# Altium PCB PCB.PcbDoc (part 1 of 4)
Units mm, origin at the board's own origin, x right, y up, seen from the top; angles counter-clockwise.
Board outline 430 x 130 mm, 2 copper layers (Top Layer, Bottom Layer); 471 components, 267 nets, 1806 pads, 471 vias.
Unrouted connection lines stored in the file: 127.
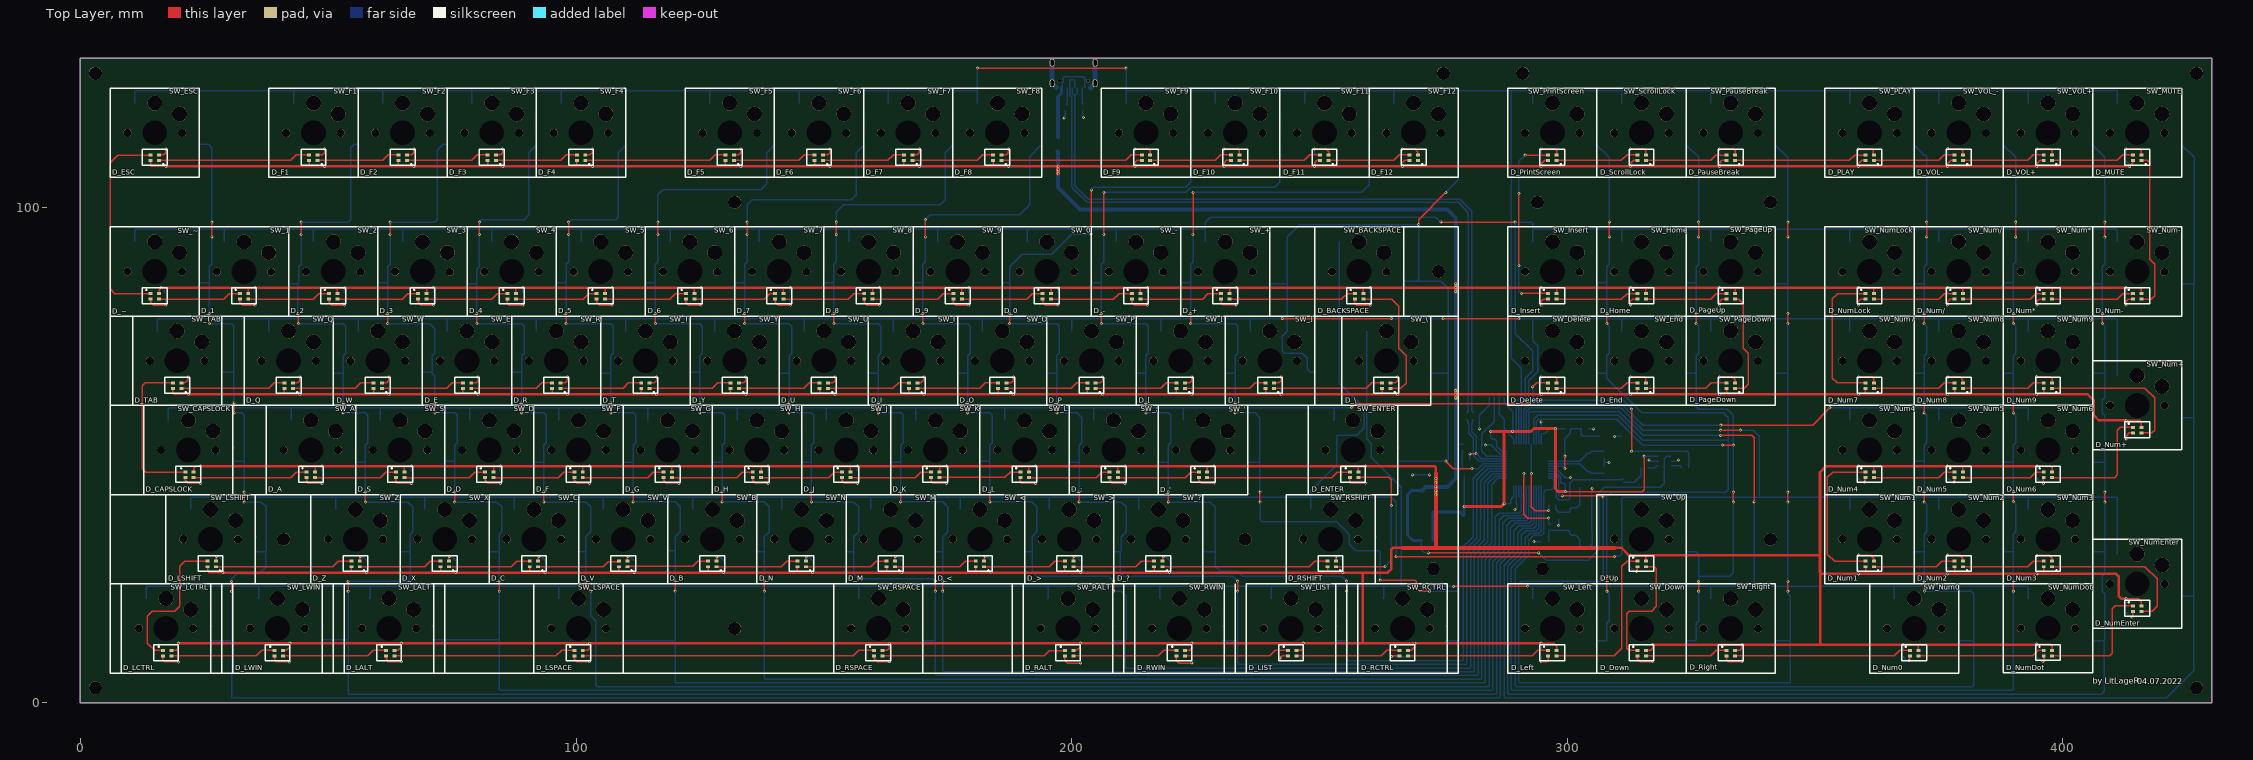
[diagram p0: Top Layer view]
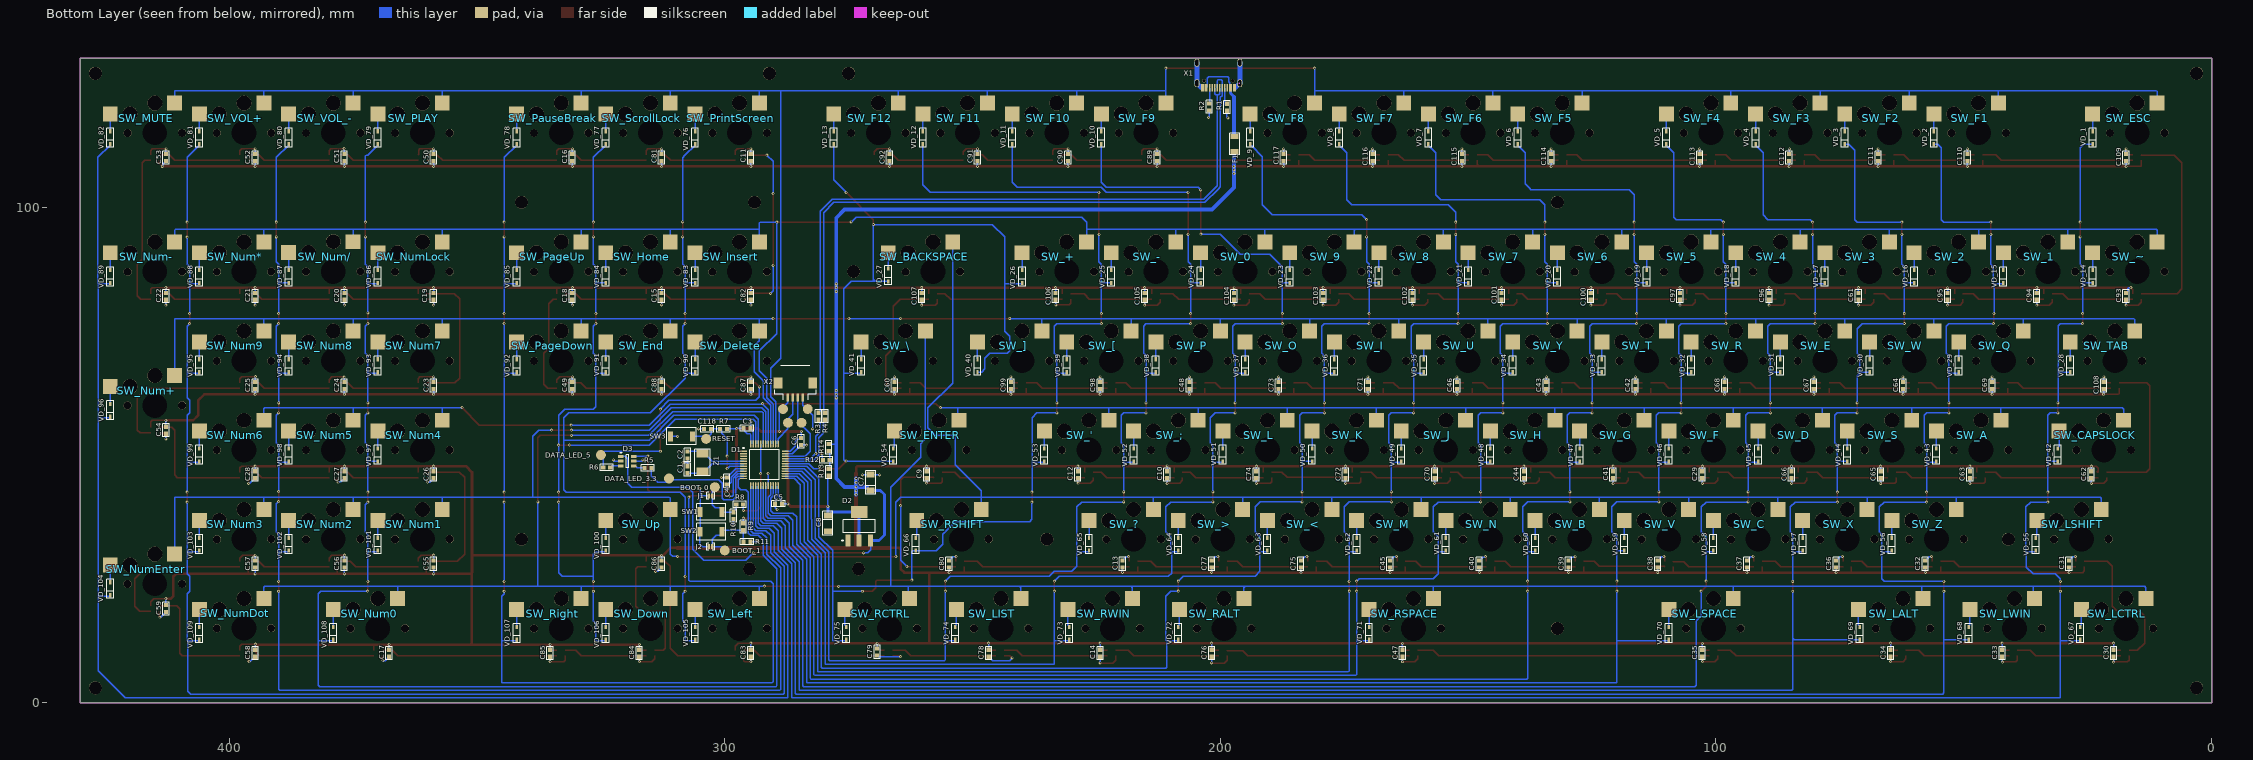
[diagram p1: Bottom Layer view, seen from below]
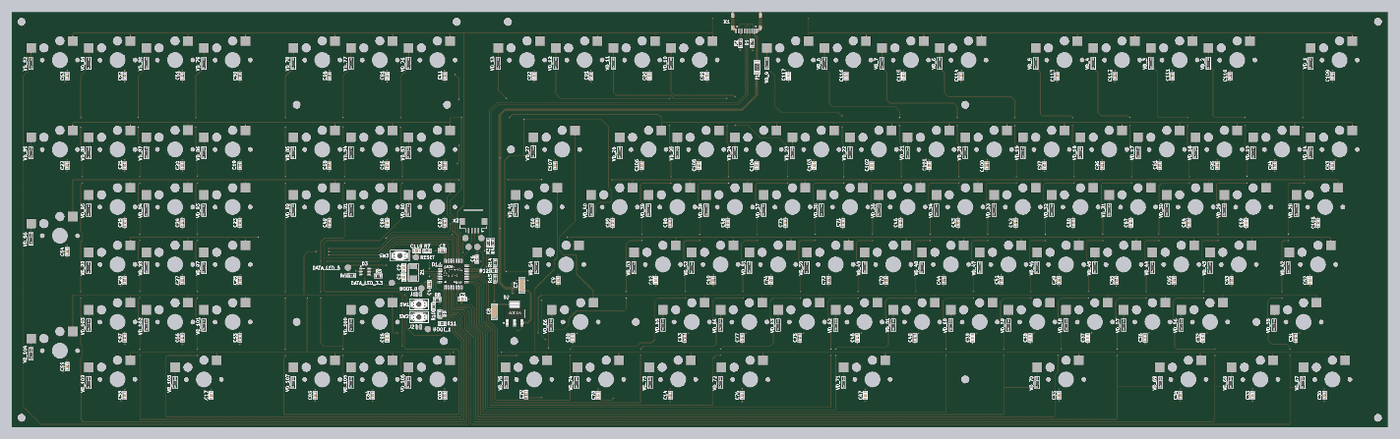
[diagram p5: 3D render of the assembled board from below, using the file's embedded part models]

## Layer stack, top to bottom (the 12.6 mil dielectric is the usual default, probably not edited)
Top Solder: solder mask 0.0102, Solder Resist, Dk 3.5
Top Layer: signal copper 0.0356
Dielectric 1: dielectric 0.32, FR-4, Dk 4.8
Bottom Layer: signal copper 0.0356
Bottom Solder: solder mask 0.0102, Solder Resist, Dk 3.5

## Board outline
0,0 0,130 430,130 430,0

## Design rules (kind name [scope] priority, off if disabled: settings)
Clearance [All] p1: gap=0.127 ignorepadtopadclearanceinfootprint=FALSE except(0: Arc-Hole Track-Hole SMDPad-Hole THPad-Hole Via-Hole Fill-Hole Poly-Hole Region-Hole Text-Hole)
DiffPairsRouting [All] p1: maxlimit=0.254 minlimit=0.254 mostfreqgap=0.254 toplayer_minwidth=0.381 toplayer_maxwidth=0.381 toplayer_prefwidth=0.381 bottomlayer_minwidth=0.381 bottomlayer_maxwidth=0.381 bottomlayer_prefwidth=0.381 maxuncoupledlength=12.7
PolygonConnect [All] p1: connectstyle=Relief reliefconductorwidth=0.254 reliefentries=4 polygonreliefangle="90 Angle" airgapwidth=0.254
RoutingVias [All] p1: holewidth=0.711 width=1.27 viastyle="Through Hole" minholewidth=0.711 minwidth=1.27 maxholewidth=0.711 maxwidth=1.27
SolderMaskExpansion [All] p1: expansion=0.102 istentingtop=FALSE
Width [All] p1: maxlimit=0.254 minlimit=0.254 preferedwidth=0.254
29 further rules are at their usual default settings.

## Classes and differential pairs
differential pair DU: +DU_P -DU_N

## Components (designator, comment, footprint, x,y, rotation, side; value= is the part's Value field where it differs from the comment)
C1 "#NAME?" "CAP: 0603" 307.5,47 r270 bottom value=20pF
C2 "#NAME?" "CAP: 0603" 307.5,50 r90 bottom value=20pF
C3 "#NAME?" "CAP: 0603" 295.5,55.375 r0 bottom value=0.1μF
C4 "#NAME?" "CAP: 0603" 299.575,44.75 r270 bottom value=0.1μF
C5 "#NAME?" "CAP: 0603" 289.15,40.15 r180 bottom value=0.1μF
C6 "#NAME?" "CAP: 0603" 284.625,52.725 r90 bottom value=0.1μF
C7 "#NAME?" "CAP: TANTAL-A" 270.55,44.45 r90 bottom value=10μF
C8 "#NAME?" "CAP: TANTAL-A" 279.2,36.2 r270 bottom value=10μF
C9 "#NAME?" "CAP: 0603" 259.25,46 r90 bottom value=0.1μF
C10 "#NAME?" "CAP: 0603" 210.75,46 r90 bottom value=0.1μF
C11 "#NAME?" "CAP: 0603" 294.75,110 r270 bottom value=0.1μF
C12 "#NAME?" "CAP: 0603" 228.75,46 r90 bottom value=0.1μF
C13 "#NAME?" "CAP: 0603" 219.75,28 r270 bottom value=0.1μF
C14 "#NAME?" "CAP: 0603" 224.25,10 r90 bottom value=0.1μF
C15 "#NAME?" "CAP: 0603" 312.75,82 r90 bottom value=0.1μF
C16 "#NAME?" "CAP: 0603" 330.75,110 r270 bottom value=0.1μF
C17 "#NAME?" "CAP: 0603" 367.75,10 r90 bottom value=0.1μF
C18 "#NAME?" "CAP: 0603" 330.75,82 r90 bottom value=0.1μF
C19 "#NAME?" "CAP: 0603" 358.75,82 r90 bottom value=0.1μF
C20 "#NAME?" "CAP: 0603" 376.75,82 r90 bottom value=0.1μF
C21 "#NAME?" "CAP: 0603" 394.75,82 r90 bottom value=0.1μF
C22 "#NAME?" "CAP: 0603" 412.75,82 r90 bottom value=0.1μF
C23 "#NAME?" "CAP: 0603" 358.75,64 r270 bottom value=0.1μF
C24 "#NAME?" "CAP: 0603" 376.75,64 r270 bottom value=0.1μF
C25 "#NAME?" "CAP: 0603" 394.75,64 r270 bottom value=0.1μF
C26 "#NAME?" "CAP: 0603" 358.75,46 r90 bottom value=0.1μF
C27 "#NAME?" "CAP: 0603" 376.75,46 r90 bottom value=0.1μF
C28 "#NAME?" "CAP: 0603" 394.75,46 r90 bottom value=0.1μF
C29 "#NAME?" "CAP: 0603" 102.75,46 r90 bottom value=0.1μF
C30 "#NAME?" "CAP: 0603" 19.75,10 r90 bottom value=0.1μF
C31 "#NAME?" "CAP: 0603" 28.75,28 r270 bottom value=0.1μF
C32 "#NAME?" "CAP: 0603" 57.75,28 r270 bottom value=0.1μF
C33 "#NAME?" "CAP: 0603" 42.25,10 r90 bottom value=0.1μF
C34 "#NAME?" "CAP: 0603" 64.75,10 r90 bottom value=0.1μF
C35 "#NAME?" "CAP: 0603" 102.75,10 r90 bottom value=0.1μF
C36 "#NAME?" "CAP: 0603" 75.75,28 r270 bottom value=0.1μF
C37 "#NAME?" "CAP: 0603" 93.75,28 r270 bottom value=0.1μF
C38 "#NAME?" "CAP: 0603" 111.75,28 r270 bottom value=0.1μF
C39 "#NAME?" "CAP: 0603" 129.75,28 r270 bottom value=0.1μF
C40 "#NAME?" "CAP: 0603" 147.75,28 r270 bottom value=0.1μF
C41 "#NAME?" "CAP: 0603" 120.75,46 r90 bottom value=0.1μF
C42 "#NAME?" "CAP: 0603" 116.25,64 r270 bottom value=0.1μF
C43 "#NAME?" "CAP: 0603" 134.25,64 r270 bottom value=0.1μF
C44 "#NAME?" "CAP: 0603" 138.75,46 r90 bottom value=0.1μF
C45 "#NAME?" "CAP: 0603" 165.75,28 r270 bottom value=0.1μF
C46 "#NAME?" "CAP: 0603" 152.25,64 r270 bottom value=0.1μF
C47 "#NAME?" "CAP: 0603" 163.25,10 r90 bottom value=0.1μF
C48 "#NAME?" "CAP: 0603" 206.25,64 r270 bottom value=0.1μF
C49 "#NAME?" "CAP: 0603" 330.75,64 r270 bottom value=0.1μF
C50 "#NAME?" "CAP: 0603" 358.75,110 r270 bottom value=0.1μF
C51 "#NAME?" "CAP: 0603" 376.75,110 r270 bottom value=0.1μF
C52 "#NAME?" "CAP: 0603" 394.75,110 r270 bottom value=0.1μF
C53 "#NAME?" "CAP: 0603" 412.75,110 r270 bottom value=0.1μF
C54 "#NAME?" "CAP: 0603" 412.75,55 r90 bottom value=0.1μF
C55 "#NAME?" "CAP: 0603" 358.75,28 r270 bottom value=0.1μF
C56 "#NAME?" "CAP: 0603" 376.75,28 r270 bottom value=0.1μF
C57 "#NAME?" "CAP: 0603" 394.75,28 r270 bottom value=0.1μF
C58 "#NAME?" "CAP: 0603" 394.75,10 r90 bottom value=0.1μF
C59 "#NAME?" "CAP: 0603" 412.75,19 r90 bottom value=0.1μF
C60 "#NAME?" "CAP: 0603" 265.75,64 r270 bottom value=0.1μF
C61 "#NAME?" "CAP: 0603" 71.25,82 r90 bottom value=0.1μF
C62 "#NAME?" "CAP: 0603" 24.25,46 r90 bottom value=0.1μF
C63 "#NAME?" "CAP: 0603" 48.75,46 r90 bottom value=0.1μF
C64 "#NAME?" "CAP: 0603" 62.25,64 r270 bottom value=0.1μF
C65 "#NAME?" "CAP: 0603" 66.75,46 r90 bottom value=0.1μF
C66 "#NAME?" "CAP: 0603" 84.75,46 r90 bottom value=0.1μF
C67 "#NAME?" "CAP: 0603" 80.25,64 r270 bottom value=0.1μF
C68 "#NAME?" "CAP: 0603" 98.25,64 r270 bottom value=0.1μF
C69 "#NAME?" "CAP: 0603" 44.25,64 r270 bottom value=0.1μF
C70 "#NAME?" "CAP: 0603" 156.75,46 r90 bottom value=0.1μF
C71 "#NAME?" "CAP: 0603" 170.25,64 r270 bottom value=0.1μF
C72 "#NAME?" "CAP: 0603" 174.75,46 r90 bottom value=0.1μF
C73 "#NAME?" "CAP: 0603" 188.25,64 r270 bottom value=0.1μF
C74 "#NAME?" "CAP: 0603" 192.75,46 r90 bottom value=0.1μF
C75 "#NAME?" "CAP: 0603" 183.75,28 r270 bottom value=0.1μF
C76 "#NAME?" "CAP: 0603" 201.75,10 r90 bottom value=0.1μF
C77 "#NAME?" "CAP: 0603" 201.75,28 r270 bottom value=0.1μF
C78 "#NAME?" "CAP: 0603" 246.75,10 r90 bottom value=0.1μF
C79 "#NAME?" "CAP: 0603" 269.25,10.25 r90 bottom value=0.1μF
C80 "#NAME?" "CAP: 0603" 254.75,28 r270 bottom value=0.1μF
C81 "#NAME?" "CAP: 0603" 312.75,110 r270 bottom value=0.1μF
C82 "#NAME?" "CAP: 0603" 294.75,82 r90 bottom value=0.1μF
C83 "#NAME?" "CAP: 0603" 294.75,10 r90 bottom value=0.1μF
C84 "#NAME?" "CAP: 0603" 317.25,10 r90 bottom value=0.1μF
C85 "#NAME?" "CAP: 0603" 335.25,10 r90 bottom value=0.1μF
C86 "#NAME?" "CAP: 0603" 312.75,28 r90 bottom value=0.1μF
C87 "#NAME?" "CAP: 0603" 294.75,64 r270 bottom value=0.1μF
C88 "#NAME?" "CAP: 0603" 312.75,64 r270 bottom value=0.1μF
C89 "#NAME?" "CAP: 0603" 212.75,110 r270 bottom value=0.1μF
C90 "#NAME?" "CAP: 0603" 230.75,110 r270 bottom value=0.1μF
C91 "#NAME?" "CAP: 0603" 249,110 r270 bottom value=0.1μF
C92 "#NAME?" "CAP: 0603" 266.75,110 r270 bottom value=0.1μF
C93 "#NAME?" "CAP: 0603" 17.25,82 r90 bottom value=0.1μF
C94 "#NAME?" "CAP: 0603" 35.25,82 r90 bottom value=0.1μF
C95 "#NAME?" "CAP: 0603" 53.25,82 r90 bottom value=0.1μF
C96 "#NAME?" "CAP: 0603" 89.25,82 r90 bottom value=0.1μF
C97 "#NAME?" "CAP: 0603" 107.25,82 r90 bottom value=0.1μF
C98 "#NAME?" "CAP: 0603" 224.25,64 r270 bottom value=0.1μF
C99 "#NAME?" "CAP: 0603" 242.25,64 r270 bottom value=0.1μF
C100 "#NAME?" "CAP: 0603" 125.25,82 r90 bottom value=0.1μF
C101 "#NAME?" "CAP: 0603" 143.25,82 r90 bottom value=0.1μF
C102 "#NAME?" "CAP: 0603" 161.25,82 r90 bottom value=0.1μF
C103 "#NAME?" "CAP: 0603" 179.25,82 r90 bottom value=0.1μF
C104 "#NAME?" "CAP: 0603" 197.25,82 r90 bottom value=0.1μF
C105 "#NAME?" "CAP: 0603" 215.25,82 r90 bottom value=0.1μF
C106 "#NAME?" "CAP: 0603" 233.25,82 r90 bottom value=0.1μF
C107 "#NAME?" "CAP: 0603" 260.25,82 r90 bottom value=0.1μF
C108 "#NAME?" "CAP: 0603" 21.75,64 r270 bottom value=0.1μF
C109 "#NAME?" "CAP: 0603" 17.25,110 r270 bottom value=0.1μF
C110 "#NAME?" "CAP: 0603" 49.25,110 r270 bottom value=0.1μF
C111 "#NAME?" "CAP: 0603" 67.25,110 r270 bottom value=0.1μF
C112 "#NAME?" "CAP: 0603" 85.25,110 r270 bottom value=0.1μF
C113 "#NAME?" "CAP: 0603" 103.25,110 r270 bottom value=0.1μF
C114 "#NAME?" "CAP: 0603" 133.25,110 r270 bottom value=0.1μF
C115 "#NAME?" "CAP: 0603" 151.25,110 r270 bottom value=0.1μF
C116 "#NAME?" "CAP: 0603" 169.25,110 r270 bottom value=0.1μF
C117 "#NAME?" "CAP: 0603" 187.25,110 r270 bottom value=0.1μF
C118 "#NAME?" "CAP: 0603" 303.5,55.25 r180 bottom value=1μF
D1 "#NAME?" 48-LQFP 292,48 r180 bottom
D2 "#NAME?" SOT223 272.875,35.625 r90 bottom
D3 "IC CAN transceiver, 1Mbps, Half-duplex, 3...3.6V, -40...+85°C, 8-SOIC" SOT23-6 319.646,48.748 r180 bottom
D_0 "#NAME?" "LED: 2020" 195,82 r0 top
D_1 "#NAME?" "LED: 2020" 33,82 r0 top
D_2 "#NAME?" "LED: 2020" 51,82 r0 top
D_3 "#NAME?" "LED: 2020" 69,82 r0 top
D_4 "#NAME?" "LED: 2020" 87,82 r0 top
D_5 "#NAME?" "LED: 2020" 105,82 r0 top
D_6 "#NAME?" "LED: 2020" 123,82 r0 top
D_7 "#NAME?" "LED: 2020" 141,82 r0 top
D_8 "#NAME?" "LED: 2020" 159,82 r0 top
D_9 "#NAME?" "LED: 2020" 177,82 r0 top
D_' "#NAME?" "LED: 2020" 226.5,46 r0 top
D_+ "#NAME?" "LED: 2020" 231,82 r0 top
D_- "#NAME?" "LED: 2020" 213,82 r0 top
D_; "#NAME?" "LED: 2020" 208.5,46 r0 top
D_< "#NAME?" "LED: 2020" 181.5,28 r180 top
D_> "#NAME?" "LED: 2020" 199.5,28 r180 top
D_? "#NAME?" "LED: 2020" 217.5,28 r180 top
D_[ "#NAME?" "LED: 2020" 222,64 r180 top
D_\ "#NAME?" "LED: 2020" 263.5,64 r180 top
D_] "#NAME?" "LED: 2020" 240,64 r180 top
D_A "#NAME?" "LED: 2020" 46.5,46 r0 top
D_B "#NAME?" "LED: 2020" 127.5,28 r180 top
D_BACKSPACE "#NAME?" "LED: 2020" 258,82 r0 top
D_C "#NAME?" "LED: 2020" 91.5,28 r180 top
D_CAPSLOCK "#NAME?" "LED: 2020" 22,46 r0 top
D_D "#NAME?" "LED: 2020" 82.5,46 r0 top
D_Delete "#NAME?" "LED: 2020" 297,64 r180 top
D_Down "#NAME?" "LED: 2020" 315,10 r0 top
D_E "#NAME?" "LED: 2020" 78,64 r180 top
D_End "#NAME?" "LED: 2020" 315,64 r180 top
D_ENTER "#NAME?" "LED: 2020" 257,46 r0 top
D_ESC "#NAME?" "LED: 2020" 15,110 r180 top
D_F "#NAME?" "LED: 2020" 100.5,46 r0 top
D_F1 "#NAME?" "LED: 2020" 47,110 r180 top
D_F2 "#NAME?" "LED: 2020" 65,110 r180 top
D_F3 "#NAME?" "LED: 2020" 83,110 r180 top
D_F4 "#NAME?" "LED: 2020" 101,110 r180 top
D_F5 "#NAME?" "LED: 2020" 131,110 r180 top
D_F6 "#NAME?" "LED: 2020" 149,110 r180 top
D_F7 "#NAME?" "LED: 2020" 167,110 r180 top
D_F8 "#NAME?" "LED: 2020" 185,110 r180 top
D_F9 "#NAME?" "LED: 2020" 215,110 r180 top
D_F10 "#NAME?" "LED: 2020" 233,110 r180 top
D_F11 "#NAME?" "LED: 2020" 251,110 r180 top
D_F12 "#NAME?" "LED: 2020" 269,110 r180 top
D_G "#NAME?" "LED: 2020" 118.5,46 r0 top
D_H "#NAME?" "LED: 2020" 136.5,46 r0 top
D_Home "#NAME?" "LED: 2020" 315,82 r0 top
D_I "#NAME?" "LED: 2020" 168,64 r180 top
D_Insert "#NAME?" "LED: 2020" 297,82 r0 top
D_J "#NAME?" "LED: 2020" 154.5,46 r0 top
D_K "#NAME?" "LED: 2020" 172.5,46 r0 top
D_L "#NAME?" "LED: 2020" 190.5,46 r0 top
D_LALT "#NAME?" "LED: 2020" 62.5,10 r0 top
D_LCTRL "#NAME?" "LED: 2020" 17.5,10 r0 top
D_Left "#NAME?" "LED: 2020" 297,10 r0 top
D_LIST "#NAME?" "LED: 2020" 244.5,10 r0 top
D_LSHIFT "#NAME?" "LED: 2020" 26.5,28 r180 top
D_LSPACE "#NAME?" "LED: 2020" 100.5,10 r0 top
D_LWIN "#NAME?" "LED: 2020" 40,10 r0 top
D_M "#NAME?" "LED: 2020" 163.5,28 r180 top
D_MUTE "#NAME?" "LED: 2020" 415,110 r180 top
D_N "#NAME?" "LED: 2020" 145.5,28 r180 top
D_Num0 "#NAME?" "LED: 2020" 370,10 r0 top
D_Num1 "#NAME?" "LED: 2020" 361,28 r180 top
D_Num2 "#NAME?" "LED: 2020" 379,28 r180 top
D_Num3 "#NAME?" "LED: 2020" 397,28 r180 top
D_Num4 "#NAME?" "LED: 2020" 361,46 r0 top
D_Num5 "#NAME?" "LED: 2020" 379,46 r0 top
D_Num6 "#NAME?" "LED: 2020" 397,46 r0 top
D_Num7 "#NAME?" "LED: 2020" 361,64 r180 top
D_Num8 "#NAME?" "LED: 2020" 379,64 r180 top
D_Num9 "#NAME?" "LED: 2020" 397,64 r180 top
D_Num* "#NAME?" "LED: 2020" 397,82 r0 top
D_Num+ "#NAME?" "LED: 2020" 415,55 r0 top
D_Num- "#NAME?" "LED: 2020" 415,82 r0 top
D_Num/ "#NAME?" "LED: 2020" 379,82 r0 top
D_NumDot "#NAME?" "LED: 2020" 397,10 r0 top
D_NumEnter "#NAME?" "LED: 2020" 415,19 r0 top
D_NumLock "#NAME?" "LED: 2020" 361,82 r0 top
D_O "#NAME?" "LED: 2020" 186,64 r180 top
D_P "#NAME?" "LED: 2020" 204,64 r180 top
D_PageDown "#NAME?" "LED: 2020" 333,64 r180 top
D_PageUp "#NAME?" "LED: 2020" 333,82 r0 top
D_PauseBreak "#NAME?" "LED: 2020" 333,110 r180 top
D_PLAY "#NAME?" "LED: 2020" 361,110 r180 top
D_PrintScreen "#NAME?" "LED: 2020" 297,110 r180 top
D_Q "#NAME?" "LED: 2020" 42,64 r180 top
D_R "#NAME?" "LED: 2020" 96,64 r180 top
D_RALT "#NAME?" "LED: 2020" 199.5,10 r0 top
D_RCTRL "#NAME?" "LED: 2020" 267,10 r0 top
D_Right "#NAME?" "LED: 2020" 333,10 r0 top
D_RSHIFT "#NAME?" "LED: 2020" 252.5,28 r180 top
D_RSPACE "#NAME?" "LED: 2020" 161,10 r0 top
D_RWIN "#NAME?" "LED: 2020" 222,10 r0 top
D_S "#NAME?" "LED: 2020" 64.5,46 r0 top
D_ScrollLock "#NAME?" "LED: 2020" 315,110 r180 top
D_T "#NAME?" "LED: 2020" 114,64 r180 top
D_TAB "#NAME?" "LED: 2020" 19.5,64 r180 top
D_U "#NAME?" "LED: 2020" 150,64 r180 top
D_Up "#NAME?" "LED: 2020" 315,28 r0 top (schematic designator D_UP)
D_V "#NAME?" "LED: 2020" 109.5,28 r180 top
D_VOL+ "#NAME?" "LED: 2020" 397,110 r180 top
D_VOL- "#NAME?" "LED: 2020" 379,110 r180 top
D_W "#NAME?" "LED: 2020" 60,64 r180 top
D_X "#NAME?" "LED: 2020" 73.5,28 r180 top
D_Y "#NAME?" "LED: 2020" 132,64 r180 top
D_Z "#NAME?" "LED: 2020" 55.5,28 r180 top
D_~ "#NAME?" "LED: 2020" 15,82 r0 top
F1 "Resistor film, 1A, , 1206, 0.25W, -55...+125°C" "RES: 1206" 197.1,112.75 r270 bottom value=1A
J1 "" "CON: JUMPER x1" 303.2,41.75 r180 bottom
J2 "" "CON: JUMPER x1" 303.2,31.5 r180 bottom
R1 "Resistor film, 1K, , 0603, 0.1W, -55...+125°C" "RES: 0603" 198.675,120.175 r90 bottom value=1K
R2 "Resistor film, 1K, , 0603, 0.1W, -55...+125°C" "RES: 0603" 202.225,120.225 r90 bottom value=1K
R3 "Resistor film, 1K, , 0603, 0.1W, -55...+125°C" "RES: 0603" 281.1,57.8 r270 bottom value=20R
R4 "Resistor film, 1K, , 0603, 0.1W, -55...+125°C" "RES: 0603" 279.7,57.8 r270 bottom value=20R
R5 "Resistor film, 270R, , 0603, 0.1W, -55...+125°C" "RES: 0603" 315.5,47.375 r180 bottom value=270R
R6 "Resistor film, 270R, , 0603, 0.1W, -55...+125°C" "RES: 0603" 323.825,47.45 r180 bottom value=270R
R7 "Resistor film, 270R, , 0603, 0.1W, -55...+125°C" "RES: 0603" 300.25,55.25 r180 bottom value=10K
R8 "Resistor film, 270R, , 0603, 0.1W, -55...+125°C" "RES: 0603" 297,40 r0 bottom value=10K
R9 "Resistor film, 270R, , 0603, 0.1W, -55...+125°C" "RES: 0603" 296.25,35.5 r270 bottom value=10K
R10 "Resistor film, 270R, , 0603, 0.1W, -55...+125°C" "RES: 0603" 298.25,37.75 r270 bottom value=10K
R11 "Resistor film, 270R, , 0603, 0.1W, -55...+125°C" "RES: 0603" 295.5,32.5 r180 bottom value=10K
R12 "Resistor film, 270R, , 0603, 0.1W, -55...+125°C" "RES: 0603" 279.5,49 r180 bottom value=4.7K
R13 "Resistor film, 270R, , 0603, 0.1W, -55...+125°C" "RES: 0603" 279,46.5 r270 bottom value=0
R14 "Resistor film, 270R, , 0603, 0.1W, -55...+125°C" "RES: 0603" 279,51.5 r90 bottom value=0
SW1 "#NAME?" "BUT: 3x4x2 SMT" 302.75,38.5 r180 bottom
SW2 "#NAME?" "BUT: 3x4x2 SMT" 302.75,34.5 r180 bottom
SW3 "#NAME?" "BUT: 3x4x2 SMT" 308.75,53.75 r0 bottom
SW_0 "#NAME?" "BUT: kailh" 195,87 r180 top
SW_1 "#NAME?" "BUT: kailh" 33,87 r180 top
SW_2 "#NAME?" "BUT: kailh" 51,87 r180 top
SW_3 "#NAME?" "BUT: kailh" 69,87 r180 top
SW_4 "#NAME?" "BUT: kailh" 87,87 r180 top
SW_5 "#NAME?" "BUT: kailh" 105,87 r180 top
SW_6 "#NAME?" "BUT: kailh" 123,87 r180 top
SW_7 "#NAME?" "BUT: kailh" 141,87 r180 top
SW_8 "#NAME?" "BUT: kailh" 159,87 r180 top
SW_9 "#NAME?" "BUT: kailh" 177,87 r180 top
SW_' "#NAME?" "BUT: kailh" 226.5,51 r180 top
SW_+ "#NAME?" "BUT: kailh" 231,87 r180 top
SW_- "#NAME?" "BUT: kailh" 213,87 r180 top
SW_; "#NAME?" "BUT: kailh" 208.5,51 r180 top
SW_< "#NAME?" "BUT: kailh" 181.5,33 r180 top
SW_> "#NAME?" "BUT: kailh" 199.5,33 r180 top
SW_? "#NAME?" "BUT: kailh" 217.5,33 r180 top
SW_[ "#NAME?" "BUT: kailh" 222,69 r180 top
SW_\ "#NAME?" "BUT: kailh" 263.5,69 r180 top
SW_] "#NAME?" "BUT: kailh" 240,69 r180 top
SW_A "#NAME?" "BUT: kailh" 46.5,51 r180 top
SW_B "#NAME?" "BUT: kailh" 127.5,33 r180 top
SW_BACKSPACE "#NAME?" "BUT: kailh" 258,87 r180 top
SW_C "#NAME?" "BUT: kailh" 91.5,33 r180 top
SW_CAPSLOCK "#NAME?" "BUT: kailh" 21.75,51 r180 top
SW_D "#NAME?" "BUT: kailh" 82.5,51 r180 top
SW_Delete "#NAME?" "BUT: kailh" 297,69 r180 top
SW_Down "#NAME?" "BUT: kailh" 315,15 r180 top
SW_E "#NAME?" "BUT: kailh" 78,69 r180 top
SW_End "#NAME?" "BUT: kailh" 315,69 r180 top
SW_ENTER "#NAME?" "BUT: kailh" 256.75,51 r180 top
SW_ESC "#NAME?" "BUT: kailh" 15,115 r180 top
SW_F "#NAME?" "BUT: kailh" 100.5,51 r180 top
SW_F1 "#NAME?" "BUT: kailh" 47,115 r180 top
SW_F2 "#NAME?" "BUT: kailh" 65,115 r180 top
SW_F3 "#NAME?" "BUT: kailh" 83,115 r180 top
SW_F4 "#NAME?" "BUT: kailh" 101,115 r180 top
SW_F5 "#NAME?" "BUT: kailh" 131,115 r180 top
SW_F6 "#NAME?" "BUT: kailh" 149,115 r180 top
SW_F7 "#NAME?" "BUT: kailh" 167,115 r180 top
SW_F8 "#NAME?" "BUT: kailh" 185,115 r180 top
SW_F9 "#NAME?" "BUT: kailh" 215,115 r180 top
SW_F10 "#NAME?" "BUT: kailh" 233,115 r180 top
SW_F11 "#NAME?" "BUT: kailh" 251,115 r180 top
SW_F12 "#NAME?" "BUT: kailh" 269,115 r180 top
SW_G "#NAME?" "BUT: kailh" 118.5,51 r180 top
SW_H "#NAME?" "BUT: kailh" 136.5,51 r180 top
SW_Home "#NAME?" "BUT: kailh" 315,87 r180 top
SW_I "#NAME?" "BUT: kailh" 168,69 r180 top
SW_Insert "#NAME?" "BUT: kailh" 297,87 r180 top
SW_J "#NAME?" "BUT: kailh" 154.5,51 r180 top
SW_K "#NAME?" "BUT: kailh" 172.5,51 r180 top
SW_L "#NAME?" "BUT: kailh" 190.5,51 r180 top
SW_LALT "#NAME?" "BUT: kailh" 62.25,15 r180 top
SW_LCTRL "#NAME?" "BUT: kailh" 17.25,15 r180 top
SW_Left "#NAME?" "BUT: kailh" 297,15 r180 top
SW_LIST "#NAME?" "BUT: kailh" 244.25,15 r180 top
SW_LSHIFT "#NAME?" "BUT: kailh" 26.25,33 r180 top
SW_LSPACE "#NAME?" "BUT: kailh" 100.5,15 r180 top
SW_LWIN "#NAME?" "BUT: kailh" 39.75,15 r180 top
SW_M "#NAME?" "BUT: kailh" 163.5,33 r180 top
SW_MUTE "#NAME?" "BUT: kailh" 415,115 r180 top
SW_N "#NAME?" "BUT: kailh" 145.5,33 r180 top
SW_Num0 "#NAME?" "BUT: kailh" 370,15 r180 top
SW_Num1 "#NAME?" "BUT: kailh" 361,33 r180 top
SW_Num2 "#NAME?" "BUT: kailh" 379,33 r180 top
SW_Num3 "#NAME?" "BUT: kailh" 397,33 r180 top
SW_Num4 "#NAME?" "BUT: kailh" 361,51 r180 top
SW_Num5 "#NAME?" "BUT: kailh" 379,51 r180 top
SW_Num6 "#NAME?" "BUT: kailh" 397,51 r180 top
SW_Num7 "#NAME?" "BUT: kailh" 361,69 r180 top
SW_Num8 "#NAME?" "BUT: kailh" 379,69 r180 top
SW_Num9 "#NAME?" "BUT: kailh" 397,69 r180 top
SW_Num* "#NAME?" "BUT: kailh" 397,87 r180 top
SW_Num+ "#NAME?" "BUT: kailh" 415,60 r180 top
SW_Num- "#NAME?" "BUT: kailh" 415,87 r180 top
SW_Num/ "#NAME?" "BUT: kailh" 379.003,87.029 r180 top
SW_NumDot "#NAME?" "BUT: kailh" 397.003,15.029 r180 top
SW_NumEnter "#NAME?" "BUT: kailh" 415,24 r180 top
SW_NumLock "#NAME?" "BUT: kailh" 361,87 r180 top
SW_O "#NAME?" "BUT: kailh" 186,69 r180 top
SW_P "#NAME?" "BUT: kailh" 204,69 r180 top
SW_PageDown "#NAME?" "BUT: kailh" 333,69 r180 top
SW_PageUp "#NAME?" "BUT: kailh" 333,87 r180 top
SW_PauseBreak "#NAME?" "BUT: kailh" 333,115 r180 top
SW_PLAY "#NAME?" "BUT: kailh" 361,115 r180 top
SW_PrintScreen "#NAME?" "BUT: kailh" 297,115 r180 top
SW_Q "#NAME?" "BUT: kailh" 42,69 r180 top
SW_R "#NAME?" "BUT: kailh" 96,69 r180 top
SW_RALT "#NAME?" "BUT: kailh" 199.25,15 r180 top
SW_RCTRL "#NAME?" "BUT: kailh" 266.75,15 r180 top
SW_Right "#NAME?" "BUT: kailh" 333,15 r180 top
SW_RSHIFT "#NAME?" "BUT: kailh" 252.25,33 r180 top
SW_RSPACE "#NAME?" "BUT: kailh" 161,15 r180 top
SW_RWIN "#NAME?" "BUT: kailh" 221.75,15 r180 top
SW_S "#NAME?" "BUT: kailh" 64.5,51 r180 top
SW_ScrollLock "#NAME?" "BUT: kailh" 315,115 r180 top
SW_T "#NAME?" "BUT: kailh" 114,69 r180 top
SW_TAB "#NAME?" "BUT: kailh" 19.5,69 r180 top
SW_U "#NAME?" "BUT: kailh" 150,69 r180 top
SW_Up "#NAME?" "BUT: kailh" 315,33 r180 top (schematic designator SW_UP)
SW_V "#NAME?" "BUT: kailh" 109.5,33 r180 top
SW_VOL+ "#NAME?" "BUT: kailh" 397,115 r180 top
SW_VOL_- "#NAME?" "BUT: kailh" 379,115 r180 top
SW_W "#NAME?" "BUT: kailh" 60,69 r180 top
SW_X "#NAME?" "BUT: kailh" 73.5,33 r180 top
SW_Y "#NAME?" "BUT: kailh" 132,69 r180 top
SW_Z "#NAME?" "BUT: kailh" 55.5,33 r180 top
SW_~ "#NAME?" "BUT: kailh" 15,87 r180 top
VD_1 "#NAME?" "DIODE: SOD323" 24,114 r270 bottom
VD_2 "#NAME?" "DIODE: SOD323" 56,114 r270 bottom
VD_3 "#NAME?" "DIODE: SOD323" 74,114 r270 bottom
VD_4 "#NAME?" "DIODE: SOD323" 92,114 r270 bottom
VD_5 "#NAME?" "DIODE: SOD323" 110,114 r270 bottom
VD_6 "#NAME?" "DIODE: SOD323" 140,114 r270 bottom
VD_7 "#NAME?" "DIODE: SOD323" 158,114 r270 bottom
VD_8 "#NAME?" "DIODE: SOD323" 176,114 r270 bottom
VD_9 "#NAME?" "DIODE: SOD323" 194,114 r270 bottom
VD_10 "#NAME?" "DIODE: SOD323" 224,114 r270 bottom
VD_11 "#NAME?" "DIODE: SOD323" 242,114 r270 bottom
VD_12 "#NAME?" "DIODE: SOD323" 260,114 r270 bottom
VD_13 "#NAME?" "DIODE: SOD323" 278,114 r270 bottom
VD_14 "#NAME?" "DIODE: SOD323" 24,86 r270 bottom
VD_15 "#NAME?" "DIODE: SOD323" 42,86 r270 bottom
VD_16 "#NAME?" "DIODE: SOD323" 60,86 r270 bottom
VD_17 "#NAME?" "DIODE: SOD323" 78,86 r270 bottom
VD_18 "#NAME?" "DIODE: SOD323" 96,86 r270 bottom
VD_19 "#NAME?" "DIODE: SOD323" 114,86 r270 bottom
VD_20 "#NAME?" "DIODE: SOD323" 132,86 r270 bottom
VD_21 "#NAME?" "DIODE: SOD323" 150,86 r270 bottom
VD_22 "#NAME?" "DIODE: SOD323" 168,86 r270 bottom
VD_23 "#NAME?" "DIODE: SOD323" 186,86 r270 bottom
VD_24 "#NAME?" "DIODE: SOD323" 204,86 r270 bottom
VD_25 "#NAME?" "DIODE: SOD323" 222,86 r270 bottom
VD_26 "#NAME?" "DIODE: SOD323" 240,86 r270 bottom
VD_27 "#NAME?" "DIODE: SOD323" 267,86.3 r270 bottom
VD_28 "#NAME?" "DIODE: SOD323" 28.5,68 r270 bottom
VD_29 "#NAME?" "DIODE: SOD323" 51,68 r270 bottom
VD_30 "#NAME?" "DIODE: SOD323" 69,68 r270 bottom
VD_31 "#NAME?" "DIODE: SOD323" 87,68 r270 bottom
VD_32 "#NAME?" "DIODE: SOD323" 105,68 r270 bottom
VD_33 "#NAME?" "DIODE: SOD323" 123,68 r270 bottom
VD_34 "#NAME?" "DIODE: SOD323" 141,68 r270 bottom
VD_35 "#NAME?" "DIODE: SOD323" 159,68 r270 bottom
VD_36 "#NAME?" "DIODE: SOD323" 177,68 r270 bottom
VD_37 "#NAME?" "DIODE: SOD323" 195,68 r270 bottom
VD_38 "#NAME?" "DIODE: SOD323" 213,68 r270 bottom
VD_39 "#NAME?" "DIODE: SOD323" 231,68 r270 bottom
VD_40 "#NAME?" "DIODE: SOD323" 249,68 r270 bottom
VD_41 "#NAME?" "DIODE: SOD323" 272.5,68 r270 bottom
VD_42 "#NAME?" "DIODE: SOD323" 31,50 r270 bottom
VD_43 "#NAME?" "DIODE: SOD323" 55.5,50 r270 bottom
VD_44 "#NAME?" "DIODE: SOD323" 73.5,50 r270 bottom
VD_45 "#NAME?" "DIODE: SOD323" 91.5,50 r270 bottom
VD_46 "#NAME?" "DIODE: SOD323" 109.5,50 r270 bottom
VD_47 "#NAME?" "DIODE: SOD323" 127.5,50 r270 bottom
VD_48 "#NAME?" "DIODE: SOD323" 145.5,50 r270 bottom
VD_49 "#NAME?" "DIODE: SOD323" 163.5,50 r270 bottom
VD_50 "#NAME?" "DIODE: SOD323" 181.5,50 r270 bottom
VD_51 "#NAME?" "DIODE: SOD323" 199.5,50 r270 bottom
VD_52 "#NAME?" "DIODE: SOD323" 217.5,50 r270 bottom
VD_53 "#NAME?" "DIODE: SOD323" 235.5,50 r270 bottom
VD_54 "#NAME?" "DIODE: SOD323" 266,50 r270 bottom
VD_55 "#NAME?" "DIODE: SOD323" 35.5,32 r270 bottom
VD_56 "#NAME?" "DIODE: SOD323" 64.5,32 r270 bottom
VD_57 "#NAME?" "DIODE: SOD323" 82.5,32 r270 bottom
VD_58 "#NAME?" "DIODE: SOD323" 100.5,32 r270 bottom
VD_59 "#NAME?" "DIODE: SOD323" 118.5,32 r270 bottom
VD_60 "#NAME?" "DIODE: SOD323" 136.5,32 r270 bottom
VD_61 "#NAME?" "DIODE: SOD323" 154.5,32 r270 bottom
VD_62 "#NAME?" "DIODE: SOD323" 172.5,32 r270 bottom
VD_63 "#NAME?" "DIODE: SOD323" 190.5,32 r270 bottom
VD_64 "#NAME?" "DIODE: SOD323" 208.5,32 r270 bottom
VD_65 "#NAME?" "DIODE: SOD323" 226.5,32 r270 bottom
VD_66 "#NAME?" "DIODE: SOD323" 261.5,32 r270 bottom
VD_67 "#NAME?" "DIODE: SOD323" 26.5,14 r270 bottom
VD_68 "#NAME?" "DIODE: SOD323" 49,14 r270 bottom
VD_69 "#NAME?" "DIODE: SOD323" 71,14 r270 bottom
VD_70 "#NAME?" "DIODE: SOD323" 109.5,14 r270 bottom
VD_71 "#NAME?" "DIODE: SOD323" 170,14 r270 bottom
VD_72 "#NAME?" "DIODE: SOD323" 208.5,14 r270 bottom
VD_73 "#NAME?" "DIODE: SOD323" 230.5,14 r270 bottom
VD_74 "#NAME?" "DIODE: SOD323" 253.5,14 r270 bottom
VD_75 "#NAME?" "DIODE: SOD323" 275.5,14 r270 bottom
VD_76 "#NAME?" "DIODE: SOD323" 306,114 r270 bottom
VD_77 "#NAME?" "DIODE: SOD323" 324,114 r270 bottom
VD_78 "#NAME?" "DIODE: SOD323" 342,114 r270 bottom
VD_79 "#NAME?" "DIODE: SOD323" 370,114 r270 bottom
VD_80 "#NAME?" "DIODE: SOD323" 388,114 r270 bottom
VD_81 "#NAME?" "DIODE: SOD323" 406,114 r270 bottom
VD_82 "#NAME?" "DIODE: SOD323" 424,114 r270 bottom
VD_83 "#NAME?" "DIODE: SOD323" 306,86 r270 bottom
VD_84 "#NAME?" "DIODE: SOD323" 324,86 r270 bottom
VD_85 "#NAME?" "DIODE: SOD323" 342,86 r270 bottom
VD_86 "#NAME?" "DIODE: SOD323" 370,86 r270 bottom
VD_87 "#NAME?" "DIODE: SOD323" 388,86 r270 bottom
VD_88 "#NAME?" "DIODE: SOD323" 406,86 r270 bottom
VD_89 "#NAME?" "DIODE: SOD323" 424,86 r270 bottom
VD_90 "#NAME?" "DIODE: SOD323" 306,68 r270 bottom
VD_91 "#NAME?" "DIODE: SOD323" 324,68 r270 bottom
VD_92 "#NAME?" "DIODE: SOD323" 342,68 r270 bottom
VD_93 "#NAME?" "DIODE: SOD323" 370,68 r270 bottom
VD_94 "#NAME?" "DIODE: SOD323" 388,68 r270 bottom
VD_95 "#NAME?" "DIODE: SOD323" 406,68 r270 bottom
VD_96 "#NAME?" "DIODE: SOD323" 424,59 r270 bottom
VD_97 "#NAME?" "DIODE: SOD323" 370,50 r270 bottom
VD_98 "#NAME?" "DIODE: SOD323" 388,50 r270 bottom
VD_99 "#NAME?" "DIODE: SOD323" 406,50 r270 bottom
VD_100 "#NAME?" "DIODE: SOD323" 324,32 r270 bottom
VD_101 "#NAME?" "DIODE: SOD323" 370,32 r270 bottom
VD_102 "#NAME?" "DIODE: SOD323" 388,32 r270 bottom
VD_103 "#NAME?" "DIODE: SOD323" 406,32 r270 bottom
VD_104 "#NAME?" "DIODE: SOD323" 424,23 r270 bottom
VD_105 "#NAME?" "DIODE: SOD323" 306,14 r270 bottom
VD_106 "#NAME?" "DIODE: SOD323" 324,14 r270 bottom
VD_107 "#NAME?" "DIODE: SOD323" 342,14 r270 bottom
VD_108 "#NAME?" "DIODE: SOD323" 379,14 r270 bottom
VD_109 "#NAME?" "DIODE: SOD323" 406,14 r270 bottom
X1 "USB mini B" "CON: USB Type-C P16" 200.4,125 r0 bottom
X2 "#NAME?" "CON: FFC 4pin 1mm" 285.75,64.25 r0 bottom
Z1 "#NAME?" "OSC: 5032 2pins" 304.5,48.5 r90 bottom

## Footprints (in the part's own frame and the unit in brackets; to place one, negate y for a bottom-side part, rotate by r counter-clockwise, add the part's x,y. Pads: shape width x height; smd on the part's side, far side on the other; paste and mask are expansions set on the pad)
48-LQFP [mm] "QFP, 48-Leads, Body 7x7mm, Pitch 0.5mm, IPC Medium Density"
  oval 1.4x0.3 smd: 1(-4.2,2.75) 2(-4.2,2.25) 3(-4.2,1.75) 4(-4.2,1.25) 5(-4.2,0.75) 6(-4.2,0.25) 7(-4.2,-0.25) 8(-4.2,-0.75) 9(-4.2,-1.25) 10(-4.2,-1.75) 11(-4.2,-2.25) 12(-4.2,-2.75) 25(4.2,-2.75) 26(4.2,-2.25) 27(4.2,-1.75) 28(4.2,-1.25) 29(4.2,-0.75) 30(4.2,-0.25) 31(4.2,0.25) 32(4.2,0.75) 33(4.2,1.25) 34(4.2,1.75) 35(4.2,2.25) 36(4.2,2.75)
  oval 0.3x1.4 smd: 13(-2.75,-4.2) 14(-2.25,-4.2) 15(-1.75,-4.2) 16(-1.25,-4.2) 17(-0.75,-4.2) 18(-0.25,-4.2) 19(0.25,-4.2) 20(0.75,-4.2) 21(1.25,-4.2) 22(1.75,-4.2) 23(2.25,-4.2) 24(2.75,-4.2) 37(2.75,4.2) 38(2.25,4.2) 39(1.75,4.2) 40(1.25,4.2) 41(0.75,4.2) 42(0.25,4.2) 43(-0.25,4.2) 44(-0.75,4.2) 45(-1.25,4.2) 46(-1.75,4.2) 47(-2.25,4.2) 48(-2.75,4.2)
  round 0.5 on Mech1: ""(-4,4)
  silkscreen extent -4.33,-3 3,3.52, body extent -4.5,-4.5 4.5,4.5, height 1.6
"BUT: 3x4x2 SMT" [mm]
  rect 1x2 smd: 1(-2.2,0) 2(2.2,0)
  silkscreen extent -2.95,-1.7 2.95,1.7, body extent -2.45,-1.45 2.45,1.45, height 2
"BUT: kailh" [mm]
  rect 3x3 smd far side: 1(-9,-3.8) 2(4,-6)
  round 1.6 hole 1.6 unplated: 5(-5.497,0.029) 5(5.5,0)
  round 3 hole 3 unplated: 5(-5,-3.8) 5(0,-6)
  round 3 hole 5 unplated: 5(0,0)
  silkscreen extent -9,-9 9,9
"CAP: 0603" [mm]
  rect 0.85x0.85 smd: 1(-0.7,0) 2(0.7,0)
  silkscreen extent -1.33,-0.63 1.33,0.63, body extent -0.8,-0.4 0.8,0.4, height 0.3
"CAP: TANTAL-A" [mm]
  rect 1.2x1.6 smd: 1(-1.6,0) 2(1.6,0)
  silkscreen extent -2.4,-1 2.4,1, body extent -1.7,-0.84 1.7,0.84, height 1.71
"CON: FFC 4pin 1mm" [mm]
  rect 1.8x2.2 smd: 0(-3.5,-0.25) 0(3.5,-0.25)
  rect 0.5x1.6 smd: 1(-1.5,2.65) 2(-0.5,2.65) 3(0.5,2.65) 4(1.5,2.65)
  round 0.5 on Bottom Overlay: ""(-2.95,2.85)
  silkscreen extent -4.2,-3.75 4.2,3.07
"CON: JUMPER x1" [mm]
  rect 0.5x1 smd: 1(0,0) 2(0.7,0)
  silkscreen extent -0.45,-0.7 1.15,0.7
"CON: USB Type-C P16" [mm]
  round 0.65 hole 0.65: 2(-2.9,-0.5) 2(2.9,-0.5)
  rect 0.3x1.45 smd: A5(-1.25,0.9) A6(-0.25,0.9) A7(0.25,0.9) A8(1.25,0.9) B5(1.75,0.9) B6(0.75,0.9) B7(-0.75,0.9) B8(-1.75,0.9)
  oval 1x1.6 hole 0.6 slot 1.2 at 90 deg: GND1(-4.325,-4.15) GND1(-4.325,0) GND2(4.325,-4.15) GND2(4.325,0)
  rect 0.6x1.45 smd: GND1(-3.225,0.9) GND2(3.225,0.9) VCC1(-2.45,0.9) VCC2(2.45,0.9)
  Top Layer lines w0.254: -3.425,0.9 -3.225,0.9 ; 3.225,0.9 3.425,0.9
  Top Layer lines w1: -4.325,-4.15 -4.325,0 -3.425,0.9 ; 3.425,0.9 4.325,0 4.325,-4.15
  Top Layer keep-out lines w0.254: -4.325,0 -4.125,0
"DIODE: SOD323" [mm]
  rect 0.85x0.5 smd: 1(-1.3,0) 2(1.3,0)
  silkscreen extent -1.92,-0.7 1.92,0.7, body extent -1.15,-0.6 1.15,0.6, height 1.04
"LED: 2020" [mm]
  rect 0.8x0.6 smd: 1(-0.85,0.56) 2(-0.85,-0.56) 3(0.85,-0.56) 4(0.85,0.56)
  silkscreen extent -1.8,1.2 -1.6,1.4
"OSC: 5032 2pins" [mm]
  rect 1.7x2.4 smd: 1(-1.85,0) 2(1.85,0)
  silkscreen extent -2.7,-1.6 2.7,1.6
"RES: 0603" [mm]
  rect 0.85x0.85 smd: 1(-0.7,0) 2(0.7,0)
  silkscreen extent -1.33,-0.63 1.33,0.63, body extent -0.8,-0.4 0.8,0.4, height 0.44
"RES: 1206" [mm]
  rect 1x1.6 smd: 1(-1.5,0) 2(1.5,0)
  silkscreen extent -2.2,-1 2.2,1, body extent -1.65,-0.8 1.55,0.8, height 0.47
SOT23-6 [mm] "pitch 0.95 mm"
  rect 1.1x0.6 smd: 1(-1.3,0.95) 2(-1.3,0) 3(-1.3,-0.95) 4(1.3,-0.95) 5(1.3,0) 6(1.3,0.95)
  round 0.5 on Mech1: ""(-1,1.1)
  silkscreen extent -1.43,-1.3 0.25,1.82, body extent -1.4,-1.45 1.4,1.45, height 1.45
SOT223 [mm] "SOT223, 4-Leads, Body 6,50x7,00mm (avg), Pitch 2,30mm, IPC Medium Density"
  rect 2.4x1 smd: 1(-2.9,2.3) 2(-2.9,0) 3(-2.9,-2.3)
  rect 2.4x3.3 smd: 4(2.9,0)
  round 0.5 on Mech1: ""(-3,2.7)
  silkscreen extent -3.02,-3.2 1.3,3.48, body extent -3.48,-3.25 3.48,3.25, height 1.65

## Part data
C1 C2 C3 C4 C5 C6 C9 C10 C11 C12 C13 C14 C15 C16 C17 C18 C19 C20 C21 C22 C23 C24 C25 C26 C27 C28 C29 C30 C31 C32 C33 C34 C35 C36 C37 C38 C39 C40 C41 C42 C43 C44 C45 C46 C47 C48 C49 C50 C51 C52 C53 C54 C55 C56 C57 C58 C59 C60 C61 C62 C63 C64 C65 C66 C67 C68 C69 C70 C71 C72 C73 C74 C75 C76 C77 C78 C79 C80 C81 C82 C83 C84 C85 C86 C87 C88 C89 C90 C91 C92 C93 C94 C95 C96 C97 C98 C99 C100 C101 C102 C103 C104 C105 C106 C107 C108 C109 C110 C111 C112 C113 C114 C115 C116 C117 C118: library part Ceramic_0603, Manufacturer=Yageo, Package=0603, PartNumber=CC0603KRX7R7BB104, Temperature=-55...+125°C, Tolerance=±10%, TypeCapacitor="Ceramic capacitor", TypeDielectric=X7R
C7 C8: library part Tantal_A, Manufacturer=AVX, Package="case A (3216)", PartNumber=F930J107KAAAJ6, Temperature=-55...+125°C, Tolerance=±10%, TypeCapacitor="Tantalum capacitor", TypeDielectric=X7R, Voltage=16V
D1: library part STM32F103C8T6, "Cortex-M3", Manufacturer=STMicroelectronics, Package=48-LQFP, Temperature=-40...+85°C
D2: library part LDL1117S33R, "Linear voltage regulator", CurrentOutput=1.2A, Manufacturer=STMicroelectronics, Package=SOT223, Temperature=-40...+85°C, VoltageInput="input 3.9...18V", VoltageOutput="output 3.3V"
D3: library part SN74LVC1T45, "Digital isolator", Manufacturer="Texas Instruments", Package=8-SOIC, Temperature=-40...+85°C, ValueManufacturerPartNumber=#NAME?
D_0 D_1 D_2 D_3 D_4 D_5 D_6 D_7 D_8 D_9 D_' D_+ D_- D_; D_< D_> D_? D_[ D_\ D_] D_A D_B D_BACKSPACE D_C D_CAPSLOCK D_D D_Delete D_Down D_E D_End D_ENTER D_ESC D_F D_F1 D_F2 D_F3 D_F4 D_F5 D_F6 D_F7 D_F8 D_F9 D_F10 D_F11 D_F12 D_G D_H D_Home D_I D_Insert D_J D_K D_L D_LALT D_LCTRL D_Left D_LIST D_LSHIFT D_LSPACE D_LWIN D_M D_MUTE D_N D_Num0 D_Num1 D_Num2 D_Num3 D_Num4 D_Num5 D_Num6 D_Num7 D_Num8 D_Num9 D_Num* D_Num+ D_Num- D_Num/ D_NumDot D_NumEnter D_NumLock D_O D_P D_PageDown D_PageUp D_PauseBreak D_PLAY D_PrintScreen D_Q D_R D_RALT D_RCTRL D_Right D_RSHIFT D_RSPACE D_RWIN D_S D_ScrollLock D_T D_TAB D_U D_Up D_V D_VOL+ D_VOL- D_W D_X D_Y D_Z D_~: library part "YF923 2020", Current="5A peak", Manufacturer=STMicroelectronics, Package=SOT-23-6, PartNumber=WS2812, Temperature=-40...+125°C, VoltageDrop=17V
F1: library part Resistor_1206, Manufacturer=Yageo, Package=1206, PartNumber=RC1206JR-07100RL, Power=0.25W, Temperature=-55...+125°C, TypeResistor="Resistor film", ValueManufacturerPartNumber=#NAME?
J1 J2: library part Jumper_single
R1 R2 R3 R4 R5 R6 R7 R8 R9 R10 R11 R12 R13 R14: library part Resistor_0603, Manufacturer=Yageo, Package=0603, PartNumber=RC0603JR-07100RL, Power=0.1W, Temperature=-55...+125°C, TypeResistor="Resistor film", ValueManufacturerPartNumber=#NAME?
SW1 SW2 SW3: library part Button_3x4x2_SMT, "SMT 3*4*2 2PIN", Manufacturer="xin cheng electronic", Package=3*4*2mm, PartNumber="3*4*2 2PIN"
SW_0 SW_1 SW_2 SW_3 SW_4 SW_5 SW_6 SW_7 SW_8 SW_9 SW_' SW_+ SW_- SW_; SW_< SW_> SW_? SW_[ SW_\ SW_] SW_A SW_B SW_BACKSPACE SW_C SW_CAPSLOCK SW_D SW_Delete SW_Down SW_E SW_End SW_ENTER SW_ESC SW_F SW_F1 SW_F2 SW_F3 SW_F4 SW_F5 SW_F6 SW_F7 SW_F8 SW_F9 SW_F10 SW_F11 SW_F12 SW_G SW_H SW_Home SW_I SW_Insert SW_J SW_K SW_L SW_LALT SW_LCTRL SW_Left SW_LIST SW_LSHIFT SW_LSPACE SW_LWIN SW_M SW_MUTE SW_N SW_Num0 SW_Num1 SW_Num2 SW_Num3 SW_Num4 SW_Num5 SW_Num6 SW_Num7 SW_Num8 SW_Num9 SW_Num* SW_Num+ SW_Num- SW_Num/ SW_NumDot SW_NumEnter SW_NumLock SW_O SW_P SW_PageDown SW_PageUp SW_PauseBreak SW_PLAY SW_PrintScreen SW_Q SW_R SW_RALT SW_RCTRL SW_Right SW_RSHIFT SW_RSPACE SW_RWIN SW_S SW_ScrollLock SW_T SW_TAB SW_U SW_Up SW_V SW_VOL+ SW_VOL_- SW_W SW_X SW_Y SW_Z SW_~: library part Button_kailh, Manufacturer="xin cheng electronic", Package=3*4*2mm, PartNumber="3*4*2 2PIN"
VD_1 VD_2 VD_3 VD_4 VD_5 VD_6 VD_7 VD_8 VD_9 VD_10 VD_11 VD_12 VD_13 VD_14 VD_15 VD_16 VD_17 VD_18 VD_19 VD_20 VD_21 VD_22 VD_23 VD_24 VD_25 VD_26 VD_27 VD_28 VD_29 VD_30 VD_31 VD_32 VD_33 VD_34 VD_35 VD_36 VD_37 VD_38 VD_39 VD_40 VD_41 VD_42 VD_43 VD_44 VD_45 VD_46 VD_47 VD_48 VD_49 VD_50 VD_51 VD_52 VD_53 VD_54 VD_55 VD_56 VD_57 VD_58 VD_59 VD_60 VD_61 VD_62 VD_63 VD_64 VD_65 VD_66 VD_67 VD_68 VD_69 VD_70 VD_71 VD_72 VD_73 VD_74 VD_75 VD_76 VD_77 VD_78 VD_79 VD_80 VD_81 VD_82 VD_83 VD_84 VD_85 VD_86 VD_87 VD_88 VD_89 VD_90 VD_91 VD_92 VD_93 VD_94 VD_95 VD_96 VD_97 VD_98 VD_99 VD_100 VD_101 VD_102 VD_103 VD_104 VD_105 VD_106 VD_107 VD_108 VD_109: library part Schottky_single, Current=500mA, Manufacturer="Diodes Incorporated", Package=SOD-123, PartNumber=1N4148, Temperature=-55...+150°C, Voltage=80V, VoltageDrop=1V
X1: library part "Connector_USB_typeC 16P", Manufacturer=Molex, PartNumber=0675031020
X2: library part Connector_FPC_4_1mm, CurrentMax=1A, Manufacturer=JST, PartNumber=SM04B-GHS, VoltageMax=50VDC
Z1: library part Crystal_3215, Frequency=8mHz, LoadCapacitance=12.5pF, Manufacturer=Epson, Package="case 3215", PartNumber="FC-135 32.7680KA-A5", Temperature=-40...+85°C, Tolerance=±20ppm

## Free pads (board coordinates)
  round 2 smd far side: 3(283.25,59.25) 3(284.5,56.5) 3(287.25,56.5) 3(288.25,59.25) 3(300,30.75) 3(302,43.5) 3(303.75,53.25) 3(311.25,45.25) 3(325,50)
  round 2.6 hole 2.6 unplated: 4(3,3) 4(3,127) 4(41,33) 4(132,15) 4(132,101) 4(235,33) 4(273,27) 4(274,87) 4(275,127) 4(291,127) 4(294,101) 4(295,27) 4(341,33) 4(341,101) 4(427,3) 4(427,127)

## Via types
v1: diameter 0.6, hole 0.3, Top Layer to Bottom Layer, tented both sides, 471 vias

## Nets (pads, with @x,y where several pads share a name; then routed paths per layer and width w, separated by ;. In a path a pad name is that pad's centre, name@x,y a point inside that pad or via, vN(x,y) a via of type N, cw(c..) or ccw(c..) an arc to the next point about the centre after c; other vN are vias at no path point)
+3.3: C3.2 C4.2 C5.2 C6.2 C8.1 D1.9 D1.24 D1.36 D1.48 D2.2 D2.4 D3.6 J1.1 J2.1 pad.3@288.25,59.25 R7.2 R13.2 SW1.1 SW2.1 X2.4 | length 145.3
  Top Layer w0.254: 292.088,54.75 292.1,54.738 ; 292.675,54.75 292.687,54.738 ; v1(299.6,42.6) 315.1,42.6 315.5,43 v1(315.5,49.75) ; 305,42.75 v1(305,43.25)
  Top Layer w0.6: v1(279.2,39.625) 286.725,39.625 v1(287.25,40.15) 287.25,54.75 ; v1(284.55,54.75) 287.25,54.75 ; 292.675,54.75 292.088,54.75 v1(289,54.75) 287.25,54.75 ; 292.687,54.738 293.275,55.325 v1(297.625,55.325) 297.625,43.125 298.15,42.6 v1(299.6,42.6)
  Bottom Layer w0.254: C8.1@279,37.8 C8.1@279.2,37.8 ; v1(279.2,39.625) 279.2,45.75 R13.2@279.25,45.8 ; v1(284.55,54.75) 284.55,53.5 284.923,53.127 285.373,53.127 285.75,52.75 285.75,51.775 286.775,50.75 D1.36@287.8,50.75 ; v1(287.25,40.15) C5.2@288.45,40.15 288.575,40.275 288.575,40.975 289.25,41.65 D1.24@289.25,43.8 ; X2.4@287.25,61.6 287.25,60.5 289,58.75 v1(289,54.75) ; D1.48@294.75,52.2 294.75,54.101 294.899,54.25 295.43,54.25 295.935,54.754 295.935,55.11 C3.2@296.2,55.375 297.575,55.375 v1(297.625,55.325) 299.475,55.325 R7.2@299.55,55.25 ; D1.9@296.2,46.75 297.525,46.75 298.725,45.55 298.725,44.45 298.874,44.301 299.324,44.301 C4.2@299.575,44.05 299.575,42.625 v1(299.6,42.6) ; J2.1@303.2,31.5 304.5,31.5 305,32 305,34.45 SW2.1@304.95,34.5 SW1.1@304.95,38.5 304.95,41.75 ; J1.1@303.2,41.75 304.95,41.75 ; v1(305,43.25) 304.95,43.2 304.95,41.75 ; v1(315.5,49.75) 318.294,49.75 D3.6@318.346,49.698
  Bottom Layer w0.6: D2.2@272.875,32.725 D2.4@272.875,38.525 278.275,38.525 C8.1@279,37.8 ; C8.1@279.2,37.8 v1(279.2,39.625)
